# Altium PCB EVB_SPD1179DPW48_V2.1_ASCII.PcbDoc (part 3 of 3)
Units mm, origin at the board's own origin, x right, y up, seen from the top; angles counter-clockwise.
Board outline 135 x 90 mm, 4 copper layers (Top Layer, GND, L3, Bottom Layer), stack 0.603 mm thick; 322 components, 156 nets, 727 pads, 939 vias.
Unrouted connection lines stored in the file: 172.
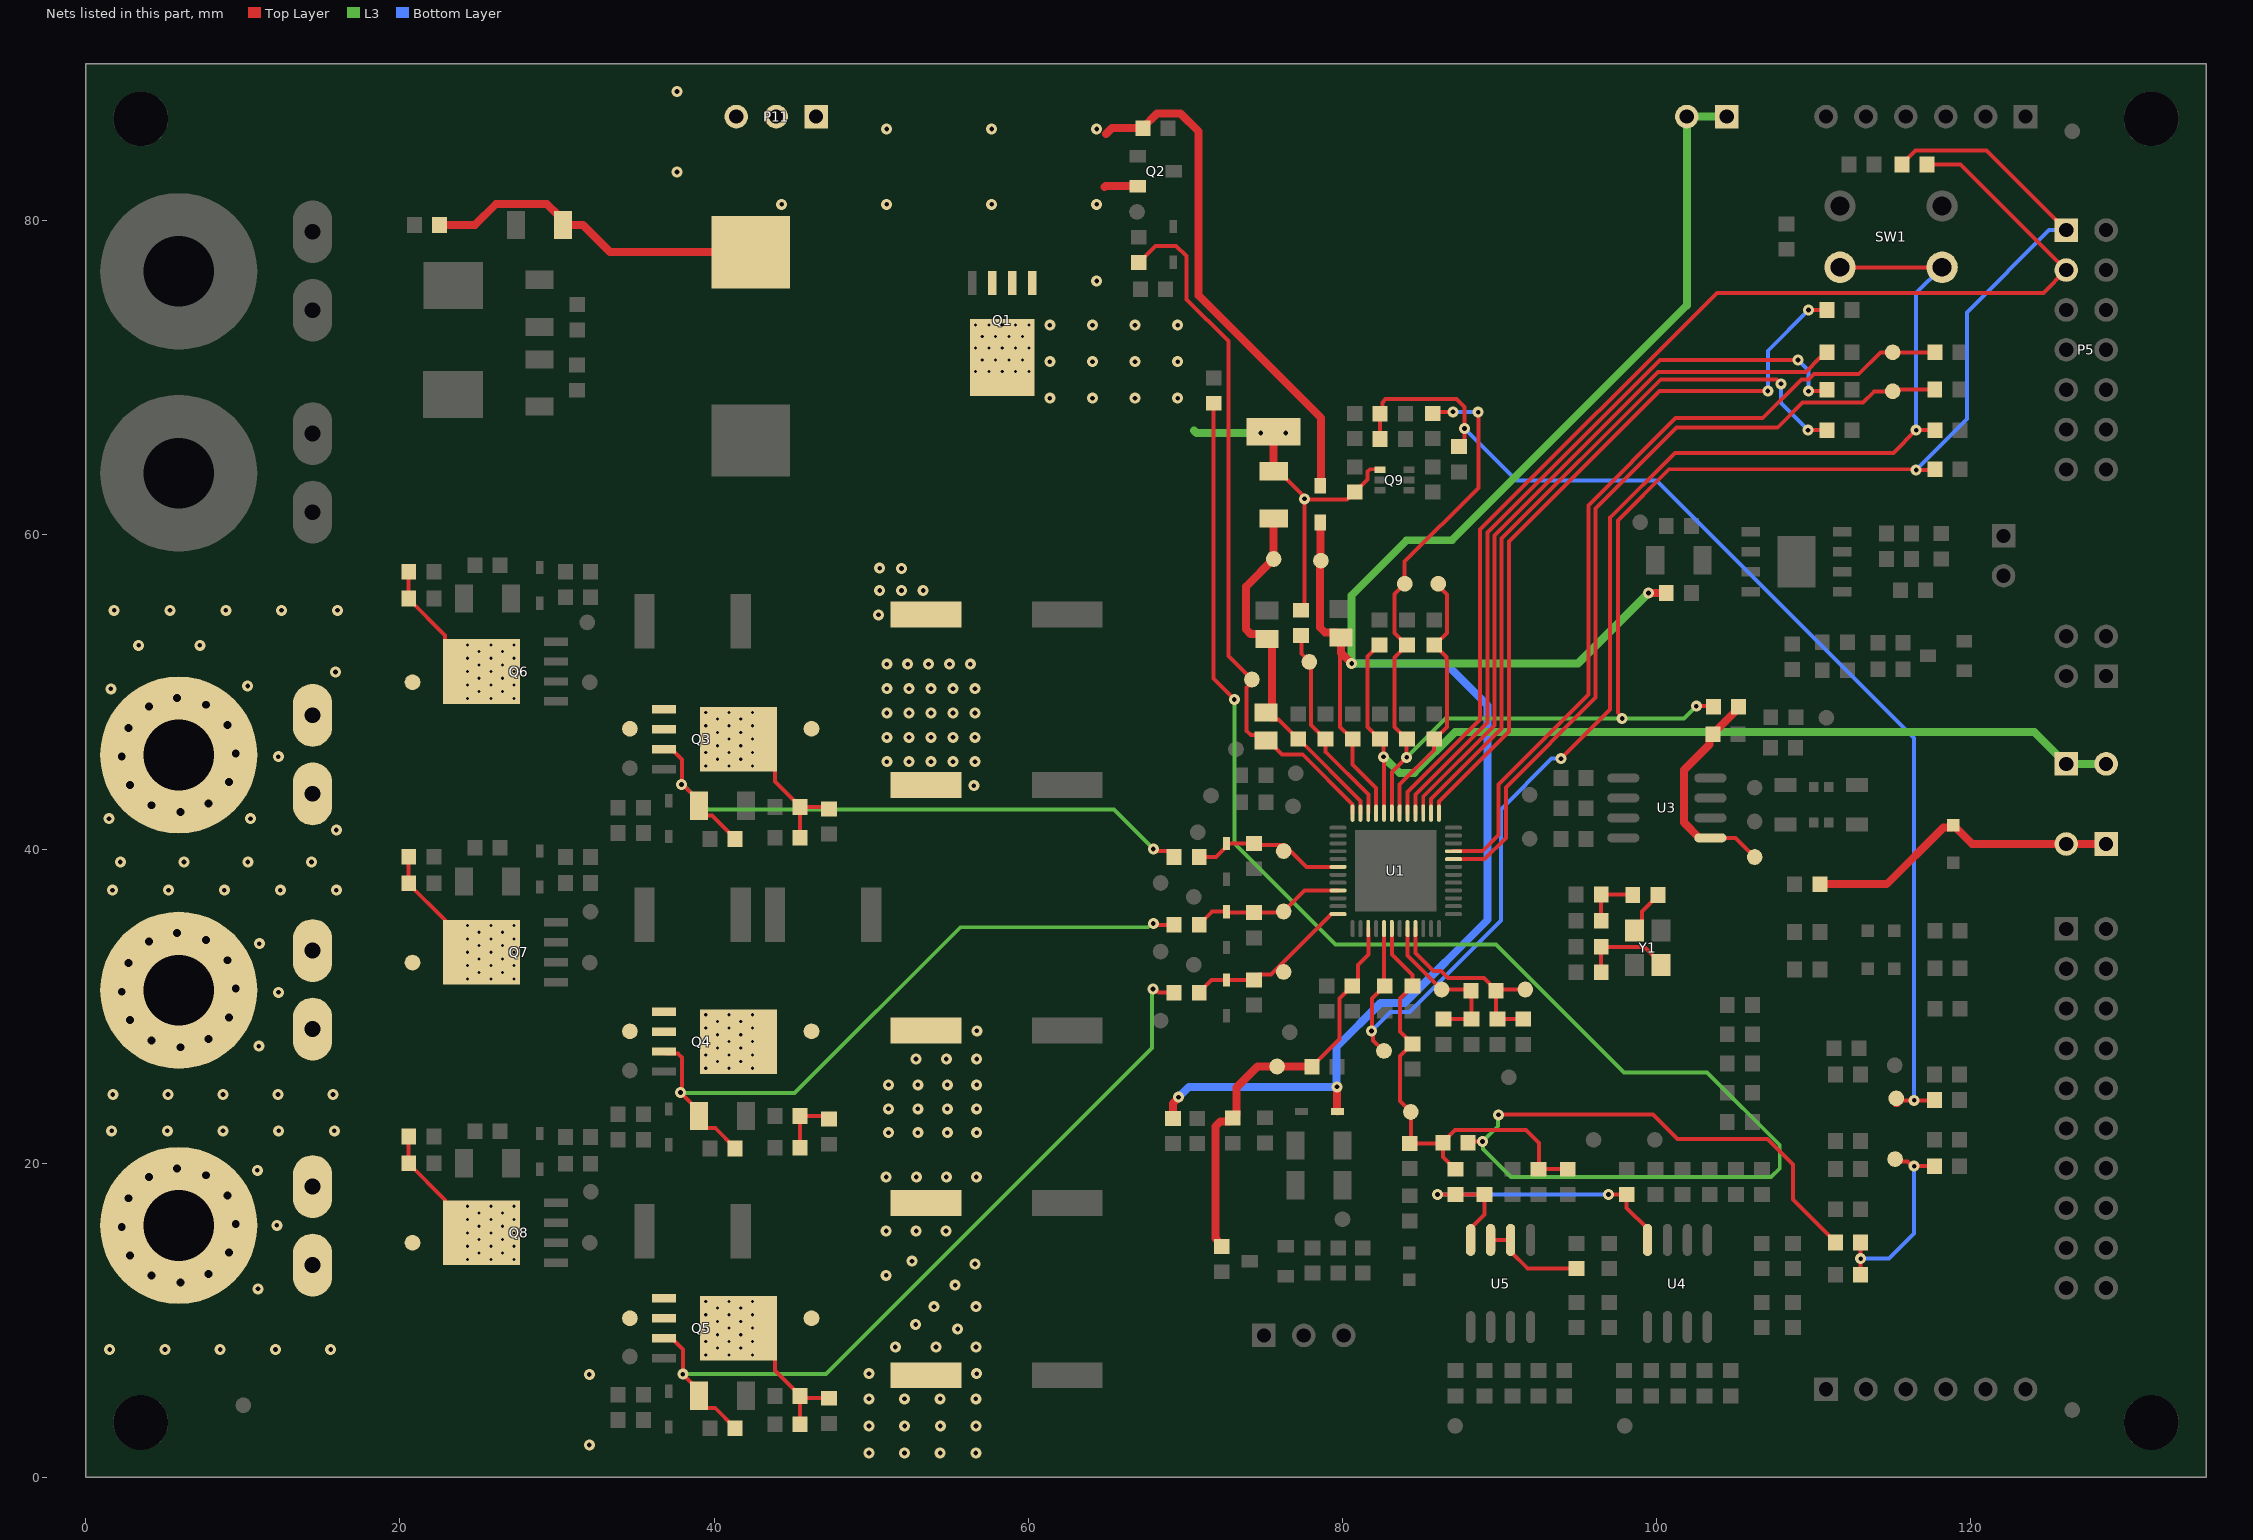
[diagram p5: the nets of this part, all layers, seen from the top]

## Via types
v1: diameter 0.7, hole 0.3, Top Layer to Bottom Layer, tented both sides, 693 vias
v2: diameter 0.5, hole 0.2, Top Layer to Bottom Layer, tented both sides, 154 vias
v3: diameter 0.9, hole 0.5, Top Layer to Bottom Layer, 60 vias
v4: diameter 0.5, hole 0.2, Top Layer to Bottom Layer, 32 vias

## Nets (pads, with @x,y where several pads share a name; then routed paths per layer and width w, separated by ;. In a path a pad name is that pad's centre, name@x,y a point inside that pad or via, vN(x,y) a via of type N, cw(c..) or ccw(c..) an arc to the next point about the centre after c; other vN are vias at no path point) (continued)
NetR107_1: R107.1 R108.1 R109.1 | length 122.3
  Top Layer w0.254: R109.1@71.806,68.39 71.806,50.851 v1(73.127,49.53) ; R107.1@87.998,21.311 88.072,21.384 v1(88.925,21.384) ; v1(89.941,23.089) 89.967,23.114 99.771,23.114 101.346,21.539 107.075,21.539 108.687,19.927 108.687,17.691 111.392,14.986 R108.1@111.392,14.961
  L3 w0.254: v1(73.127,49.53) 73.127,40.361 79.553,33.934 89.789,33.934 97.942,25.781 103.226,25.781 107.848,21.158 107.848,19.681 107.293,19.126 90.729,19.126 88.961,20.894 88.961,21.349 v1(88.925,21.384) 89.899,22.358 89.899,23.046 v1(89.941,23.089)
NetR110_2: R110.2 U5.6 U5.7 | length 6.6
  Top Layer w0.254: U5.7@89.443,15.117 U5.6@90.713,15.117 90.713,14.388 91.804,13.297 R110.2@94.904,13.297
NetR123_1: R123.1 Y1.3 | length 2.9
  Top Layer w0.254: Y1.3@98.591,34.831 99.064,35.304 99.064,36.034 100.089,37.059 R123.1@100.089,37.084
NTCAD: C73.2 NTCAD.1 R104.1 R108.2 | length 13.1
  Top Layer w0.254: C73.2@112.992,12.903 R108.2@112.992,14.961 R108.2@112.992,14.986 ; NTCAD.1@115.189,20.269 115.332,20.126 115.973,20.126 116.288,19.812 v1(116.408,19.812) R104.1@117.704,19.812
  Bottom Layer w0.254: v1(113.005,13.924) 114.812,13.924 116.408,15.519 v1(116.408,19.812)
PGAIN: C51.1 C53.2 PGAIN.1 R58.2 U1.44 | length 10.3
  Top Layer w0.254: U1.44@84.152,34.941 84.152,33.231 PGAIN.1@86.319,31.064 88.109,31.064 C51.1@88.186,30.988 88.224,30.95 R58.2@88.224,29.172 C53.2@86.446,29.172
PGAIP: C51.2 C52.2 PGAIP.1 R54.2 U1.45 | length 13.1
  Top Layer w0.254: U1.45@84.652,34.941 84.652,33.378 85.801,32.228 86.293,32.228 86.728,31.793 89.006,31.793 89.786,31.013 C51.2@89.786,30.988 ; C52.2@91.526,29.172 R54.2@89.875,29.172 89.786,29.261 C51.2@89.786,30.988 ; PGAIP.1@91.653,31.064 89.862,31.064 C51.2@89.786,30.988
PWM/LIN: D18.2 P25.1 P25.2 R21.1 | length 20.3
  Top Layer w0.508: R21.1@110.401,37.77 114.656,37.77 118.271,41.385 118.751,41.385 D18.2@118.897,41.531 120.101,40.327 P25.2@126.086,40.327 P25.1@128.626,40.327
PWM/LIN_MCU: C78.2 LIN.1 R66. R84.1 R111.1 U1.39 | length 26.8
  Top Layer w0.254: R111.1@73.025,22.873 R111.1@73.262,23.11 ; R66.@78.067,26.137 78.067,26.162 79.808,27.903 79.808,30.484 80.604,31.28 C78.2@80.629,31.28 ; C78.2@80.764,31.28 80.985,31.5 80.985,32.615 81.652,33.282 U1.39@81.652,34.941
  Top Layer w0.508: R84.1@72.314,14.694 72.289,14.694 72.068,14.915 72.068,15.077 71.933,15.212 71.933,22.354 72.23,22.652 72.804,22.652 R111.1@73.025,22.873 ; R111.1@73.262,23.11 73.262,24.824 74.6,26.162 LIN.1@75.844,26.162 R66.@78.042,26.162
TCK/SWC: R16.2 U1.16 | length 47.6
  Top Layer w0.254: U1.16@84.652,42.291 84.652,43.483 89.23,48.061 89.23,60.152 100.224,71.145 v1(109.017,71.145) ; v1(109.677,69.159) 110.777,69.159 R16.2@110.858,69.24
  Bottom Layer w0.254: v1(109.017,71.145) 109.677,70.485 v1(109.677,69.159)
TDI: R13.2 U1.13 | length 47
  Top Layer w0.254: U1.13@86.152,42.291 86.154,42.293 86.154,43.045 90.602,47.493 90.602,59.583 100.188,69.17 v1(107.086,69.17) ; v1(109.677,74.32) R13.2@110.858,74.32
  Bottom Layer w0.254: v1(107.086,69.17) 107.086,71.73 v1(109.677,74.32)
TDO: R18.2 U1.14 | length 46.3
  Top Layer w0.254: U1.14@85.652,42.291 85.652,43.189 90.145,47.682 90.145,59.773 100.273,69.901 107.65,69.901 v1(107.923,69.628) ; v1(109.652,66.675) 110.85,66.675 R18.2@110.858,66.667
  Bottom Layer w0.254: v1(107.923,69.628) 107.923,68.404 v1(109.652,66.675)
TMS/SWD: R14.2 U1.15 | length 45.6
  Top Layer w0.254: U1.15@85.152,42.291 85.152,43.336 89.687,47.872 89.687,59.962 100.109,70.383 109.513,70.383 110.385,71.255 110.51,71.255 110.858,71.603 R14.2@110.858,71.628
TRSTn: P5.3 R12.1 U1.17 | length 75.8
  Top Layer w0.254: U1.17@84.152,42.291 84.152,43.629 88.773,48.251 88.773,60.341 103.845,75.413 124.628,75.413 P5.3@126.086,76.87 119.364,83.591 R12.1@117.234,83.591
UART_RX: R15.1 RX.1 U1.9 | length 52.8
  Top Layer w0.254: U1.9@87.077,39.866 88.913,39.866 89.954,40.906 89.954,44.118 95.67,49.835 95.67,61.888 101.219,67.437 106.766,67.437 109.219,69.89 109.666,69.89 110.033,70.256 112.878,70.256 114.249,71.628 R15.1@117.729,71.628
UART_TX: R17.1 TX.1 U1.8 | length 52
  Top Layer w0.254: U1.8@87.077,39.366 89.06,39.366 90.411,40.717 90.411,43.929 96.127,49.645 96.127,61.699 101.281,66.853 107.721,66.853 109.296,68.428 113.145,68.428 113.864,69.147 TX.1@115.037,69.147 115.155,69.266 R17.1@117.716,69.266
VBAT: C35.2 C36.2 D12.1 D16.2 P10.1 P10.2 R49.1 R64.2 U1.21 VBAT.1 | length 144.6
  Top Layer w0.254: C35.2@79.908,53.481 79.856,53.429 79.856,47.783 80.636,47.003 C36.2@80.661,47.003 80.661,45.383 82.152,43.893 U1.21@82.152,42.291
  Top Layer w0.508: R64.2@69.215,22.847 69.215,23.82 69.571,24.176 v1(69.571,24.206) ; D12.1@78.595,60.798 78.595,58.412 VBAT.1@78.638,58.369 78.588,58.318 78.588,54.1 78.885,53.802 79.587,53.802 C35.2@79.908,53.481 79.908,52.502 v1(80.594,51.816) ; v1(79.654,24.867) 79.654,23.324 D16.2@79.686,23.292 ; v1(99.492,56.312) R49.1@100.622,56.312
  L3 w0.508: v1(99.492,56.312) 94.996,51.816 v1(80.594,51.816) 80.594,56.159 84.099,59.665 86.97,59.665 101.93,74.625 P10.2@101.93,86.639 P10.1@104.47,86.639
  Bottom Layer w0.508: v1(69.571,24.206) 70.231,24.867 v1(79.654,24.867) ; v1@79.642,24.892 79.642,27.419 82.433,30.21 83.957,30.21 89.256,35.509 89.256,49.149 86.589,51.816 v1(80.594,51.816)
VBAT1: C9.2 C10.1 C11.2 D12.2 L1.2 P11.1 P11.2 P11.3 Q1.1 Q1.2 Q1.3 Q2.2 | length 56.7
  Top Layer w0.508: C11.2@22.517,79.731 24.77,79.731 26.102,81.062 29.373,81.062 30.059,80.377 30.38,80.056 C10.1@30.38,79.731 31.648,79.731 33.37,78.009 L1.2@42.342,78.009 ; 64.872,82.169 64.912,82.21 Q2.2@66.973,82.21 ; 64.948,85.522 65.329,85.903 C9.2@67.297,85.903 67.297,85.928 68.204,86.835 69.706,86.835 70.841,85.7 70.841,75.26 78.638,67.462 D12.2@78.638,63.143
  other v1: 64.364,76.175 44.304,81.051 50.99,81.051 57.677,81.051 64.364,81.051 37.643,83.112 50.99,85.852 57.677,85.852 64.364,85.852 37.643,88.24
VBAT_D: C1.1 C5.1 C6.1 C14.1 C15.1 C16.2 C17.2 C18.2 C20.2 C21.2 C22.2 C56.1 C68.1 C69.1 D.1@46.203,10.135 D.1@46.203,28.397 D.1@46.203,47.66 Q1.5 Q3.5 Q4.5 Q5.5 Q9.4 R39.2 R43.1 R93.1 VBAT_D.1 | length 45
  Top Layer w0.254: v2(42.443,7.804) 43.631,7.804 43.866,7.569 43.866,6.819 45.479,5.207 C22.2@45.479,5.182 ; v2(42.443,45.301) 43.631,45.301 43.866,45.066 43.866,44.316 45.479,42.704 C20.2@45.479,42.679 ; C69.1@45.479,3.378 C22.2@45.479,5.182 ; C68.1@45.479,20.996 C21.2@45.479,23.003 47.13,23.003 C16.2@47.32,22.812 ; C56.1@45.479,40.723 C20.2@45.479,42.679 ; C18.2@47.32,5.042 45.618,5.042 C22.2@45.479,5.182 ; C17.2@47.32,42.564 47.206,42.679 C20.2@45.479,42.679 ; R43.1@75.625,64.06 75.95,64.06 v1@77.597,62.413 ; R39.2@77.368,55.207 77.597,55.435 77.597,60.041 ; 77.596,60.042 77.596,60.561 v1(77.597,62.306) v1@77.597,62.413 ; Q9.4@82.392,64.15 82.337,64.094 82.245,64.186 81.759,64.186 81.61,64.037 81.61,63.532 81.154,63.076 81.104,63.076 80.284,62.255 77.755,62.255 v1@77.597,62.413
  Top Layer w0.508: R43.1@75.625,64.06 VBAT_D.1@75.625,66.573
  L3 w0.508: 70.561,66.65 70.714,66.497 v1(74.799,66.497) v1(76.399,66.497)
  other v1: 49.86,1.549 52.129,1.549 54.398,1.549 56.667,1.549 32.055,2.057 49.86,3.277 52.132,3.277 54.404,3.277 56.676,3.277 49.86,5.004 52.129,5.004 54.398,5.004 56.667,5.004 32.055,6.553 49.86,6.604 56.718,6.604 51.537,8.306 54.131,8.306 56.676,8.306 55.506,9.451 52.832,9.728 54,10.871 56.676,10.871 55.347,12.243 50.961,12.866 56.617,13.589 52.603,13.767 50.961,15.686 52.866,15.686 54.771,15.686 50.961,19.126 52.874,19.126 54.787,19.126 56.701,19.126 51.105,21.946 52.976,21.946 54.847,21.946 56.718,21.946 51.105,23.47 52.976,23.47 54.847,23.47 56.718,23.47 51.105,24.994 52.976,24.994 54.847,24.994 56.718,24.994 52.857,26.645 54.788,26.645 56.718,26.645 56.726,28.436 56.54,44.044 51.003,45.568 52.407,45.568 53.81,45.568 55.213,45.568 56.617,45.568 51.003,47.12 52.407,47.12 53.81,47.12 55.213,47.12 56.617,47.12 51.003,48.673 52.407,48.673 53.81,48.673 55.213,48.673 56.617,48.673 51.003,50.216 52.407,50.216 53.81,50.216 55.213,50.216 56.617,50.216 51.003,51.779 52.33,51.779 53.657,51.779 54.985,51.779 56.312,51.779 50.47,54.915 50.546,56.464 51.93,56.464 53.315,56.464 51.93,57.861 50.546,57.887 61.377,68.707 64.092,68.707 66.806,68.707 69.52,68.707 61.377,71.031 64.092,71.031 66.806,71.031 69.52,71.031 61.377,73.355 64.092,73.355 66.806,73.355 69.52,73.355
  other v2: 39.472,7.804 40.957,7.804 40.215,8.23 41.7,8.23 39.472,8.655 40.957,8.655 42.443,8.655 40.215,9.081 41.7,9.081 39.472,9.506 42.443,9.506 40.215,9.931 41.7,9.931 39.472,10.357 40.957,10.357 42.443,10.357 40.215,10.782 41.7,10.782 39.472,11.208 40.957,11.208 42.443,11.208 39.472,26.053 40.957,26.053 42.443,26.053 40.215,26.478 41.7,26.478 39.472,26.904 40.957,26.904 42.443,26.904 40.215,27.329 41.7,27.329 39.472,27.754 42.443,27.754 40.215,28.18 41.7,28.18 39.472,28.605 40.957,28.605 42.443,28.605 40.215,29.031 41.7,29.031 39.472,29.456 40.957,29.456 42.443,29.456 39.472,45.301 40.957,45.301 40.215,45.727 41.7,45.727 39.472,46.152 40.957,46.152 42.443,46.152 40.215,46.577 41.7,46.577 39.472,47.003 42.443,47.003 40.215,47.428 41.7,47.428 39.472,47.854 40.957,47.854 42.443,47.854 40.215,48.279 41.7,48.279 39.472,48.705 40.957,48.705 42.443,48.705 56.648,70.409 57.499,70.409 58.35,70.409 59.201,70.409 60.052,70.409 57.074,71.152 57.925,71.152 58.776,71.152 59.627,71.152 56.648,71.895 57.499,71.895 59.201,71.895 60.052,71.895 57.074,72.638 57.925,72.638 58.776,72.638 59.627,72.638 56.648,73.381 57.499,73.381 58.35,73.381 59.201,73.381 60.052,73.381
  other v4: 40.957,9.506 40.957,27.754 40.957,47.003 58.35,71.895
VBATCP: C38.2 C39.2 C49.2 R43.2 U1.23 VBATCP.1 | length 23.5
  Top Layer w0.254: C49.2@75.143,48.603 75.491,48.255 75.923,48.255 77.175,47.003 C39.2@77.2,47.003 77.225,47.003 81.15,43.078 81.15,42.293 U1.23@81.152,42.291
  Top Layer w0.508: C49.2@75.143,48.703 75.193,48.703 75.514,49.024 75.514,53.075 74.888,53.701 74.161,53.701 73.863,53.998 73.863,56.709 VBATCP.1@75.625,58.471 R43.2@75.625,61.06
VBATD_DIV: C83.2 R87.1 R88.1 R98.1 VBATdiv.1 | length 73.1
  Top Layer w0.254: R88.1@82.41,66.116 R98.1@82.41,67.716 82.546,67.852 82.546,68.449 82.753,68.656 87.267,68.656 87.782,68.141 v1(87.782,66.777) 87.782,65.971 87.434,65.623 C83.2@87.427,65.623 ; VBATdiv.1@115.189,23.724 115.391,23.724 115.67,24.003 v1(116.408,24.003) 117.678,24.003 R87.1@117.704,24.028
  Bottom Layer w0.254: v1(87.782,66.777) 91.084,63.475 100,63.475 116.408,47.066 v1(116.408,24.003)
VBATM: C37.2 R39.1 U1.22 VBATM.1 | length 13.1
  Top Layer w0.254: R39.1@77.403,53.597 77.403,52.439 77.902,51.94 VBATM.1@77.902,51.918 78.005,51.815 78.005,47.903 78.905,47.003 C37.2@78.93,47.003 78.93,46.199 81.652,43.478 U1.22@81.652,42.291
VCAP12: C29.2 C30.2 U1.18 VCAP12.1 | length 16.8
  Top Layer w0.254: U1.18@83.652,42.291 83.652,44.104 85.843,46.296 85.843,46.994 C30.2@85.852,47.003 85.877,47.003 86.657,47.783 86.657,52.053 86.639,52.07 86.639,52.222 C29.2@85.877,52.984 ; C29.2@85.852,52.984 C29.2@85.877,52.984 ; VCAP12.1@86.106,56.896 86.106,56.752 86.657,56.201 86.657,53.764 C29.2@85.877,52.984
VCP: C49.1 R5.1 U1.24 VCP.1 | length 45.1
  Top Layer w0.254: R5.1@67.031,77.356 67.056,77.356 68.106,78.406 69.422,78.406 70.079,77.749 70.079,75.006 72.746,72.339 72.746,52.299 VCP.1@74.244,50.8 74.244,50.608 73.914,50.278 73.914,47.523 74.185,47.252 74.918,47.252 76.146,46.025 77.479,46.025 80.652,42.853 U1.24@80.652,42.291
VDD3: C40.2 C41.2 C72.2 R82.1 R96.1 R106.2 R107.2 U1.42 VDD3.1 | length 30.1
  Top Layer w0.254: U1.42@83.152,34.941 83.152,33.291 84.456,31.987 84.456,31.289 C41.2@84.464,31.28 ; C41.2@84.439,31.28 83.66,30.5 83.66,28.402 84.091,27.97 84.091,27.945 C40.2@84.439,27.597 ; R96.1@87.208,19.621 87.183,19.621 86.398,20.406 R107.2@86.398,21.311 ; C72.2@94.345,19.621 R82.1@92.491,19.621 92.466,19.621 92.527,19.682 92.527,21.283 91.694,22.115 87.178,22.115 86.398,21.336 R107.2@86.398,21.311 ; C40.2@84.439,27.597 C40.2@84.464,27.597 C40.2@84.439,27.597 ; C40.2@84.439,27.597 83.66,26.817 83.66,23.97 VDD3.1@84.363,23.266 84.363,21.336 R106.2@84.287,21.26 86.347,21.26 R107.2@86.398,21.311
VDD5: C31.2 C32.2 P5.1 R12.2 R20.2 R48.2 R97.1 U1.19 VDD5.1 | length 120.1
  Top Layer w0.254: U1.19@83.152,42.291 83.152,44.899 v1(84.099,45.847) 84.099,46.981 C32.2@84.122,47.003 84.097,47.003 83.317,47.783 83.317,52.205 C31.2@84.097,52.984 ; C31.2@84.122,52.984 C31.2@84.097,52.984 ; R97.1@85.765,67.741 85.867,67.843 v1(87.046,67.843) ; v1(88.646,67.818) 88.671,67.793 88.671,63.004 83.972,58.305 VDD5.1@83.972,56.896 83.317,56.24 83.317,53.764 C31.2@84.097,52.984 ; v1(97.815,48.311) 97.815,48.403 97.536,48.683 97.536,60.935 100.787,64.186 116.487,64.186 v1(116.532,64.141) 117.684,64.141 R20.2@117.729,64.186 ; v1(102.54,49.098) 103.594,49.098 R48.2@103.619,49.073 ; R12.2@115.634,83.591 115.634,83.616 116.49,84.472 121.023,84.472 P5.1@126.086,79.41
  L3 w0.254: v1(84.099,45.847) 86.563,48.311 v1(97.815,48.311) 101.752,48.311 v1(102.54,49.098)
  Bottom Layer w0.254: v1(87.046,67.843) 87.058,67.831 88.633,67.831 v1(88.646,67.818) ; v1(116.532,64.141) 119.761,67.37 119.761,74.168 125.003,79.41 P5.1@126.086,79.41
VDD5EXT: C33.2 C84.2 P8.1 P8.2 U1.20 | length 60.2
  Top Layer w0.254: C33.2@82.607,52.75 C33.2@82.372,52.985 82.347,52.985 81.614,52.251 81.593,52.251 81.593,47.783 82.373,47.003 C84.2@82.398,47.003 82.626,46.774 v1(82.626,45.872) 82.65,45.849 82.65,42.293 U1.20@82.652,42.291
  L3 w0.508: v1(82.626,45.872) 83.642,44.856 84.582,44.856 87.173,47.447 124.063,47.447 P8.1@126.086,45.425 P8.2@128.626,45.425
VIO: C61.2 R48.1 U3.5 VIO.1 | length 14.2
  Top Layer w0.254: U3.5@103.433,40.716 105.029,40.716 VIO.1@106.248,39.497
  Top Layer w0.508: U3.5@103.433,40.716 102.726,40.716 101.752,41.69 101.752,45.034 103.373,46.655 103.373,47.099 C61.2@103.594,47.32 103.594,47.345 104.998,48.75 104.998,48.852 R48.1@105.219,49.073
VOP: C70.2 C71.2 R96.2 U4.8 U5.8 | length 21.8
  Top Layer w0.254: v1(86.055,18.009) 87.195,18.009 R96.2@87.208,18.021 C70.2@89.057,18.021 89.057,16.73 88.173,15.845 U5.8@88.173,15.117 ; v1(96.952,18.009) 98.093,18.009 C71.2@98.106,18.021 98.106,17.165 99.427,15.845 U4.8@99.427,15.117
  Bottom Layer w0.254: v1(86.055,18.009) v1(96.952,18.009)
VPX_U: C28.1 C43.2 C79.1 D.1@20.803,14.935 P16.1 pad.1@5.918,16.042 Q5.1 Q5.2 Q5.3 Q8.5 R31.1 R37.2 S.1@34.646,10.135 | length 58.6
  Top Layer w0.254: C79.1@20.561,21.7 C43.2@20.561,19.998 20.561,19.973 22.879,17.655 22.879,17.501 23.114,17.266 v2(24.301,17.266) ; Q5.3@36.805,8.865 37.3,8.865 38.015,8.15 v1(38.015,6.568) 38.015,6.555 39.038,5.532 R37.2@39.038,5.207 39.038,4.882 39.486,4.434 40.054,4.434 41.338,3.149 C28.1@41.338,3.124 ; v1(67.947,31.091) 68.068,31.091 68.298,30.861 R31.1@69.288,30.861
  L3 w0.254: v1(38.015,6.568) 38.025,6.579 47.117,6.579 67.885,27.347 67.885,31.03 v1(67.947,31.091)
  other v1: 1.52,8.148 5.038,8.148 8.556,8.148 12.074,8.148 15.592,8.148 10.969,12.009 12.163,16.048 10.918,19.553 1.647,22.068 5.191,22.068 8.734,22.068 12.277,22.068 15.82,22.068
  other v2: 24.301,13.862 25.787,13.862 27.273,13.862 25.044,14.288 26.53,14.288 24.301,14.713 25.787,14.713 27.273,14.713 25.044,15.138 26.53,15.138 24.301,15.564 27.273,15.564 25.044,15.989 26.53,15.989 24.301,16.415 25.787,16.415 27.273,16.415 25.044,16.84 26.53,16.84 25.787,17.266 27.273,17.266
  other v3: 6.02,12.409 4.19,12.845 7.822,12.947 2.823,14.138 9.115,14.313 2.286,15.94 9.55,16.143 2.722,17.77 9.013,17.946 4.014,19.136 7.646,19.238 5.817,19.674
  other v4: 25.787,15.564
VPX_U0: C19.2 D3.1 R31.2 U1.36 VPXU.1 | length 10.9
  Top Layer w0.254: R31.2@70.888,30.861 70.888,30.886 71.673,31.671 D3.1@72.628,31.671 72.635,31.664 C19.2@74.381,31.664 74.729,32.012 75.452,32.012 79.306,35.866 U1.36@79.727,35.866
VPX_V: C27.1 C42.2 C76.1 D.1@20.803,32.779 P15.1 pad.1@5.918,31.017 Q4.1 Q4.2 Q4.3 Q7.5 R33.2 R38.1 S.1@34.646,28.397 | length 51.5
  Top Layer w0.254: C76.1@20.561,39.521 C42.2@20.561,37.819 20.561,37.794 22.879,35.477 22.879,35.37 23.114,35.135 v2(24.301,35.135) ; Q4.3@36.805,27.113 36.944,26.973 37.703,26.973 37.946,26.731 37.946,24.601 37.855,24.511 39.038,23.328 R33.2@39.038,23.003 39.038,22.678 39.486,22.23 40.079,22.23 41.338,20.971 C27.1@41.338,20.946 ; v1(67.97,35.261) 68.052,35.179 R38.1@69.288,35.179
  L3 w0.254: v1(37.86,24.511) 37.886,24.486 45.136,24.486 55.677,35.027 67.616,35.027 67.85,35.261 v1(67.97,35.261)
  other v1: 1.723,24.379 5.229,24.379 8.734,24.379 12.239,24.379 15.744,24.379 11.02,27.452 12.264,30.881 11.045,33.98 1.698,37.384 5.26,37.384 8.823,37.384 12.385,37.384 15.947,37.384
  other v2: 24.301,31.731 25.787,31.731 27.273,31.731 25.044,32.156 26.53,32.156 24.301,32.582 25.787,32.582 27.273,32.582 25.044,33.007 26.53,33.007 24.301,33.433 27.273,33.433 25.044,33.858 26.53,33.858 24.301,34.284 25.787,34.284 27.273,34.284 25.044,34.709 26.53,34.709 25.787,35.135 27.273,35.135
  other v3: 6.02,27.385 4.19,27.821 7.822,27.922 2.823,29.113 9.115,29.289 2.286,30.916 9.55,31.119 2.722,32.745 9.013,32.921 4.014,34.112 7.646,34.214 5.817,34.649
  other v4: 25.787,33.433
VPX_V0: C23.2 D4.1 R38.2 U1.33 VPXV.1 | length 9.9
  Top Layer w0.254: R38.2@70.888,35.179 70.888,35.204 71.698,36.014 D4.1@72.628,36.014 72.689,35.954 VPXV.1@76.184,35.954 ; VPXV.1@76.26,36.03 VPXV.1@76.184,35.954 ; U1.33@79.727,37.366 77.596,37.366 VPXV.1@76.184,35.954
VPX_W: C25.2 C26.1 C75.1 D.1@20.803,50.622 P14.1 pad.1@5.918,45.993 Q3.1 Q3.2 Q3.3 Q6.5 R32.2 R44.1 S.1@34.646,47.66 | length 48.4
  Top Layer w0.254: C75.1@20.561,57.658 C25.2@20.561,55.956 20.561,55.931 22.879,53.614 22.879,53.238 23.114,53.003 v2(24.301,53.003) ; Q3.3@36.805,46.362 37.3,46.362 37.961,45.701 37.961,44.159 v1(37.922,44.12) 37.998,44.12 39.038,43.08 39.038,42.587 39.486,42.139 39.871,42.139 41.338,40.672 C26.1@41.338,40.647 ; v1(67.97,40.005) 68.091,40.005 68.226,39.87 68.94,39.87 69.288,39.522 R44.1@69.288,39.497
  L3 w0.254: v1(37.922,44.12) 38.024,44.12 39.624,42.52 65.456,42.52 v1(67.97,40.005)
  other v1: 2.202,39.181 6.258,39.181 10.313,39.181 14.369,39.181 15.951,41.224 1.473,41.935 10.483,41.935 12.261,45.886 1.593,50.204 10.305,50.382 15.893,51.271 3.371,52.973 7.257,52.973 1.803,55.208 5.357,55.208 8.912,55.208 12.466,55.208 16.02,55.208
  other v2: 24.301,49.6 25.787,49.6 27.273,49.6 25.044,50.025 26.53,50.025 24.301,50.451 25.787,50.451 27.273,50.451 25.044,50.876 26.53,50.876 24.301,51.302 27.273,51.302 25.044,51.727 26.53,51.727 24.301,52.153 25.787,52.153 27.273,52.153 25.044,52.578 26.53,52.578 25.787,53.003 27.273,53.003
  other v3: 6.02,42.361 4.19,42.796 7.822,42.898 2.823,44.089 9.115,44.265 2.286,45.891 9.55,46.094 2.722,47.721 9.013,47.897 4.014,49.088 7.646,49.189 5.817,49.625
  other v4: 25.787,51.302
VPX_W0: C24.2 D5.1 R44.2 U1.30 VPXW.1 | length 9.9
  Top Layer w0.254: R44.2@70.888,39.497 71.957,39.497 72.628,40.168 D5.1@72.628,40.358 72.635,40.351 C24.2@74.381,40.351 ; C24.2@74.381,40.272 76.326,40.272 77.731,38.866 U1.30@79.727,38.866
XIN: C12.2 R1.1 Y1.1 | length 6
  Top Layer w0.254: C12.2@96.482,32.156 R1.1@96.482,33.782 99.24,33.782 100.291,32.731 Y1.1@100.291,32.631
XOUT: C13.2 R120.1 R123.2 | length 3.7
  Top Layer w0.254: R120.1@96.482,35.433 C13.2@96.482,37.109 98.463,37.109 R123.2@98.489,37.084 R123.2@98.489,37.059
XRSTn: C7.2 R19.1 SW1.3 SW1.4 U1.41 XRSTn.1 | length 89
  Top Layer w0.254: v1(81.856,28.42) 81.941,28.335 81.941,27.831 82.509,27.263 XRSTn.1@82.509,27.153 ; v1@81.899,28.426 81.899,30.281 81.899,30.501 82.678,31.28 C7.2@82.703,31.28 82.652,31.332 U1.41@82.652,34.941 ; v1(93.918,45.756) 97.053,48.891 97.053,61.099 101.182,65.227 115.087,65.227 v1(116.535,66.675) 117.721,66.675 R19.1@117.729,66.667 ; SW1.3@111.685,77.044 SW1.4@118.185,77.044
  Bottom Layer w0.254: v1(81.856,28.42) 83.062,29.626 84.261,29.626 90.094,35.458 90.094,42.52 93.33,45.756 v1(93.918,45.756) ; v1(116.535,66.675) 116.535,75.394 SW1.4@118.185,77.044
pads on no net: MARK7.1 MARK8.1 MARK9.1 P2.17 P2.18 P2.19 P2.20 SC1.3 SC2.3 SC3.3 SC4.3 U2.3 U2.4 U2.6

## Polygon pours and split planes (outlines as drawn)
GND on Top Layer "GND_L01_P063" (solid, remove dead copper, pour order 63): 71.45,82.855 71.45,7.112 78.511,7.112 80.67,4.953 80.67,0.356 81.001,0.025 122.555,0.025 129.642,7.112 135.103,7.112 135.103,82.855 129.819,82.855 122.733,89.941 80.67,89.941 80.67,85.039 78.486,82.855
GND on Top Layer "NONET_L-01_P-001" (solid, remove dead copper, pour order 21): 0.864,82.906 0.381,82.423 0.381,71.704 1.27,70.815 18.263,70.815 20.269,72.822 35.611,72.822 35.789,73 35.789,82.982 25.349,82.982 23.317,85.014 23.317,89.154 7.163,89.154 7.163,85.014 5.055,82.906
KL30 on Top Layer "KL30_L01_P013" (solid, remove dead copper, pour order 13): 0.203,70.383 0.203,56.515 26.822,56.515 29.845,59.538 49.073,59.538 49.174,59.639 49.174,72.238 48.997,72.415 20.549,72.415 18.669,70.536 0.356,70.536
GND on Top Layer "GND_L01_P009" (solid, remove dead copper, pour order 9): 47.625,40.361 47.32,40.056 47.32,36.576 49.581,36.576 49.759,36.398 49.759,35.255 49.555,35.052 47.32,35.052 47.32,31.115 47.65,30.785 56.998,30.785 58.318,29.464 58.318,1.092 59.055,0.356 70.51,0.356 71.298,1.143 71.298,60.706 58.75,60.706 58.318,60.274 58.318,41.224 57.455,40.361
IBS+ on Top Layer "IBS+_L01_P008" (solid, remove dead copper, pour order 8): 39.472,40.107 38.964,39.599 38.964,36.627 41.046,36.627 41.275,36.398 41.275,35.179 41.148,35.052 38.964,35.052 38.964,31.09 39.218,30.836 46.584,30.836 46.939,31.191 46.939,35.052 44.475,35.052 44.171,35.357 44.171,36.449 44.298,36.576 46.939,36.576 46.939,40.056 46.888,40.107
VBAT_D on Top Layer "VBAT_D_L01_P006" (solid, remove dead copper, pour order 6): 38.456,11.913 38.456,4.343 41.758,1.041 51.054,1.041 51.054,12.548 49.708,13.894 49.555,13.741 49.555,13.386 48.743,12.573 39.116,12.573
IBS+ on Top Layer "IBS+_L01_P004" (solid, remove dead copper, pour order 4): 39.268,20.371 38.989,20.091 38.989,16.485 41.123,16.485 41.402,16.205 41.402,15.164 41.148,14.91 38.989,14.91 38.989,12.751 48.235,12.751 48.514,13.03 48.514,20.117 48.26,20.371
VPX_W on Top Layer "VPX_W_L01_P002" (solid, remove dead copper, pour order 2): 0.864,56.032 27.026,56.032 28.372,54.686 28.372,49.276 28.88,48.768 32.893,48.768 33.401,49.276 38.506,49.276 38.506,46.076 31.191,38.76 0.864,38.76
VPX_V on Top Layer "VPX_V_L01_P001" (solid, remove dead copper, pour order 1): 0.483,38.125 26.619,38.125 28.321,36.424 28.321,30.963 29.032,30.251 38.202,30.251 38.354,30.099 38.354,25.603 37.744,24.994 35.865,23.114 0.508,23.114 0.483,23.139
VPX_U on Top Layer "VPX_U_L01_P000" (solid, remove dead copper, pour order 0): 0.762,22.809 24.257,22.809 28.27,18.796 28.27,13.157 29.058,12.37 38.1,12.37 38.1,7.95 37.414,7.264 0.762,7.264
VBAT1 on Top Layer "VBAT1_L01_P014" (solid, remove dead copper, pour order 14): 36.246,88.468 36.246,73.025 63.729,73.025 65.557,74.854 65.557,88.468
VBAT_D on Top Layer "VBAT_D_L01_P012" (solid, remove dead copper, pour order 12): 39.091,49.632 38.735,49.276 38.735,44.526 42.393,40.869 57.252,40.869 57.937,41.554 57.937,60.096 59.004,61.163 71.247,61.163 71.247,73.076 69.901,74.422 51.613,74.422 49.657,72.466 49.657,51.308 47.981,49.632
IWS+ on Top Layer "IWS+_L01_P010" (solid, remove dead copper, pour order 10): 28.753,54.915 28.753,54.661 28.575,54.483 28.575,49.428 29.185,48.819 32.664,48.819 33.604,49.759 38.608,49.759 38.608,53.67 38.506,53.772 35.89,53.772 35.763,53.899 35.763,54.991 36.144,55.372 38.532,55.372 38.557,55.397 38.557,58.953 38.506,59.004 32.766,59.004 31.521,57.76
IVS+ on Top Layer "IVS+_L01_P007" (solid, remove dead copper, pour order 7): 28.626,36.373 28.626,31.217 29.261,30.582 38.125,30.582 38.43,30.886 38.43,34.9 38.303,35.027 36.17,35.027 35.814,35.382 35.814,36.373 36.068,36.627 38.405,36.627 38.481,36.703 38.481,39.776 37.77,40.488 32.487,40.488 28.88,36.881
VBAT_D on Top Layer "VBAT_D_L01_P005" (solid, remove dead copper, pour order 5): 38.938,30.455 38.71,30.226 38.71,24.816 40.462,23.063 45.872,23.063 49.276,19.66 49.276,1.067 58.014,1.067 58.014,28.931 56.49,30.455
IUS+ on Top Layer "IUS+_L01_P003" (solid, remove dead copper, pour order 3): 28.677,13.259 29.007,12.929 38.405,12.929 38.405,14.91 35.941,14.91 35.916,14.935 35.916,16.231 36.17,16.485 38.405,16.485 38.405,20.168 38.024,20.549 30.734,20.549 28.677,18.491
GND on Top Layer "GND_L01_P059" (solid, remove dead copper, pour order 59): 30.632,89.027 30.632,84.963 28.219,82.55 35.355,82.55 35.738,82.933 35.738,88.748 35.458,89.027
IBS+ on Top Layer "IBS+_L01_P011" (solid, remove dead copper, pour order 11): 39.218,58.979 39.141,58.903 39.141,55.397 39.167,55.372 41.123,55.372 41.3,55.194 41.3,53.924 41.148,53.772 38.938,53.772 38.887,53.721 38.887,49.835 47.828,49.835 49.301,51.308 49.301,58.852 49.174,58.979
GND on Bottom Layer "GND_L04_P069" (solid, remove dead copper, pour order 69): 17.247,72.619 17.247,72.339 30.15,59.436 52.095,59.436 58.42,53.111 66.246,53.111 71.247,58.112 71.247,67.691 71.044,67.894 62.332,67.894 53.95,76.276 19.863,76.276 18.821,75.235
VBAT_D on Bottom Layer "VBAT_D_L04_P068" (solid, remove dead copper, pour order 68): 55.016,74.803 71.349,74.803 71.425,74.727 71.425,68.224 71.069,67.869 55.016,67.869
VBAT_D on Bottom Layer "NONET_L-01_P-001" (solid, remove dead copper, pour order 17): 49.657,58.885 49.657,50.8 48.514,49.657 39.218,49.657 38.837,49.276 38.837,43.459 41.097,41.199 47.066,41.199 48.971,39.294 48.971,31.902 47.777,30.709 39.167,30.709 38.633,30.175 38.633,21.285 39.268,20.65 48.616,20.65 49.276,19.99 49.276,12.979 48.539,12.243 31.318,12.243 30.632,11.557 30.632,1.626 31.217,1.041 57.887,1.041 57.988,1.143 57.988,58.869
GND on Bottom Layer "GND_L04_P065" (solid, remove dead copper, pour order 65): 71.526,82.855 71.374,7.112 78.511,7.112 80.67,4.953 80.67,0.356 81.001,0.025 126.086,0.025 127.838,1.778 127.838,5.08 129.87,7.112 135.103,7.112 135.103,82.855 129.997,82.855 127.838,85.014 127.838,88.646 126.543,89.941 80.67,89.941 80.67,85.039 78.486,82.855
GND on Bottom Layer "GND_L04_P066" (solid, remove dead copper, pour order 66): 70.663,47.371 70.663,32.08 73.05,32.08 73.05,47.371
IBS+ on Bottom Layer "IBS+_L04_P015" (solid, remove dead copper, pour order 15): 29.083,57.277 31.039,59.233 49.174,59.233 49.555,58.852 49.555,51.003 48.362,49.809 39.04,49.809 38.405,49.174 38.405,43.434 40.894,40.945 46.584,40.945 48.666,38.862 48.666,32.309 47.346,30.988 39.065,30.988 39.014,31.039 38.405,30.429 38.405,20.955 39.116,20.244 48.542,20.244 49.033,19.752 49.022,19.741 49.022,13.03 48.438,12.446 30.912,12.446 29.083,14.275
GND on Bottom Layer "NONET_L-01_P-001" (solid, remove dead copper, pour order 31): 58.268,60.3 58.268,1.118 58.445,0.94 71.069,0.94 71.247,1.118 71.247,60.808 58.776,60.808
GND on Bottom Layer "NONET_L-01_P-001" (solid, remove dead copper, pour order 45): 1.041,82.982 1.041,71.069 1.295,70.815 18.415,70.815 20.396,72.796 49.098,72.796 51.765,75.463 51.841,75.387 71.349,75.387 71.349,88.875 70.968,89.256 30.886,89.256 30.632,89.002 30.632,85.014 28.778,83.16 25.222,83.16 23.368,85.014 23.368,89.586 7.137,89.586 7.137,84.988 5.131,82.982
VPX_U on Bottom Layer "NONET_L-01_P-001" (solid, remove dead copper, pour order 20): 1.067,22.809 1.067,7.239 28.092,7.239 28.702,7.849 28.702,22.301 28.194,22.809 27.889,22.809
VPX_W on Bottom Layer "NONET_L-01_P-001" (solid, remove dead copper, pour order 18): 27.915,56.032 1.016,56.032 1.016,38.735 27.94,38.735 28.473,39.268 28.473,55.474
KL30 on Bottom Layer "NONET_L-01_P-001" (solid, remove dead copper, pour order 32): 1.118,70.587 1.118,56.54 27.711,56.54 28.575,57.404 28.575,60.706 18.669,70.612 1.143,70.612
VPX_V on Bottom Layer "NONET_L-01_P-001" (solid, remove dead copper, pour order 19): 1.041,38.318 1.041,23.317 28.092,23.317 28.524,23.749 28.524,37.871 28.158,38.238
VBAT_D on L3 "VBAT_D_L03_P050" (solid, remove dead copper, pour order 50): 17.297,71.044 16.942,70.688 16.942,7.29 17.043,7.188 28.931,7.188 30.658,5.461 30.658,1.549 31.293,0.914 31.318,0.94 56.464,0.94 57.074,1.549 57.074,60.503 58.064,61.493 70.917,61.493 71.171,61.747 71.171,74.549 51.46,74.549 49.809,72.898 19.152,72.898
GND on L3 "GND_L03_P064" (solid, remove dead copper, pour order 64): 71.399,82.855 71.399,7.112 78.511,7.112 80.67,4.953 80.67,0.356 81.001,0.025 126.086,0.025 127.838,1.778 127.838,5.08 129.87,7.112 135.103,7.112 135.103,82.855 129.997,82.855 127.838,85.014 127.838,88.646 126.543,89.941 80.67,89.941 80.67,85.039 78.486,82.855
GND on L3 "GND_L03_P051" (solid, remove dead copper, pour order 51): 57.785,60.3 57.785,1.27 57.988,1.067 71.171,1.067 71.323,1.219 71.298,1.245 71.298,61.036 58.522,61.036
IBS+ on L3 "NONET_L-01_P-001" (solid, remove dead copper, pour order 24): 37.948,40.462 37.338,40.462 36.881,40.005 36.881,32.029 38.202,30.709 47.93,30.709 49.251,32.029 49.251,39.802 48.618,40.434
IBS+ on L3 "NONET_L-01_P-001" (solid, remove dead copper, pour order 23): 37.135,58.674 36.601,58.141 36.601,50.902 37.44,50.063 48.59,50.063 49.53,51.003 49.53,58.141 48.997,58.674
VBAT1 on L3 "NONET_L-01_P-001" (solid, remove dead copper, pour order 33): 36.246,88.316 36.246,73.508 50.013,73.508 51.74,75.235 71.145,75.235 71.145,88.316
IBS+ on L3 "IBS+_L03_P046" (solid, remove dead copper, pour order 46): 38.354,19.71 38.354,12.7 38.532,12.522 48.006,12.522 48.59,13.106 48.59,19.837 47.549,20.879 39.548,20.879 38.76,20.091
GND on L3 "GND_L03_P060" (solid, remove dead copper, pour order 60): 30.582,89.51 30.582,84.328 32.918,84.328 35.789,87.198 35.789,89.256 35.535,89.51
VPX_U on L3 "VPX_U_L03_P056" (solid, remove dead copper, pour order 56): 1.041,22.733 1.041,7.163 16.535,7.163 16.662,7.29 16.662,22.682 16.485,22.86 1.168,22.86
VPX_V on L3 "VPX_V_L03_P055" (solid, remove dead copper, pour order 55): 1.067,38.252 1.067,23.317 16.637,23.317 16.739,23.419 16.739,37.973 16.459,38.252
VPX_W on L3 "VPX_W_L03_P054" (solid, remove dead copper, pour order 54): 1.041,56.032 1.041,38.684 16.612,38.684 16.713,38.786 16.713,55.905 16.586,56.032
KL30 on L3 "KL30_L03_P053" (solid, remove dead copper, pour order 53): 1.118,70.637 1.067,70.587 1.067,56.54 16.332,56.54 16.535,56.744 16.535,70.358 16.256,70.637
VPX_W on L3 "VPX_W_L03_P049" (solid, remove dead copper, pour order 49): 23.876,53.492 23.876,49.073 27.838,49.073 27.838,53.492
VPX_V on L3 "VPX_V_L03_P048" (solid, remove dead copper, pour order 48): 23.876,35.623 23.876,31.204 27.838,31.204 27.838,35.623
VPX_U on L3 "VPX_U_L03_P047" (solid, remove dead copper, pour order 47): 23.876,17.755 23.876,13.335 27.838,13.335 27.838,17.755
GND on L3 "NONET_L-01_P-001" (solid, remove dead copper, pour order 34): 0.965,82.931 0.965,71.069 1.092,70.942 18.567,70.942 20.726,73.101 35.408,73.101 35.789,73.482 35.789,87.198 34.372,88.615 28.791,83.16 25.222,83.16 23.368,85.014 23.368,89.306 7.163,89.306 7.163,85.039 5.055,82.931
GND on GND "NONET_L-01_P-001" (solid, remove dead copper, pour order 43): 1.092,82.906 1.092,7.442 1.372,7.163 29.032,7.163 30.937,5.258 30.937,1.397 31.369,0.965 71.069,0.965 71.247,1.143 71.247,89.51 31.115,89.51 30.582,88.976 30.582,84.938 28.804,83.16 25.171,83.16 23.343,84.988 23.343,88.646 22.377,89.611 7.569,89.611 7.163,89.205 7.163,85.039 5.105,82.982 1.168,82.982
GND on GND "GND_L02_P062" (solid, remove dead copper, pour order 62): 71.577,82.855 71.425,7.112 78.511,7.112 80.67,4.953 80.67,0.356 81.001,0.025 126.086,0.025 127.838,1.778 127.838,5.08 129.87,7.112 135.103,7.112 135.103,82.855 129.997,82.855 127.838,85.014 127.838,88.646 126.543,89.941 80.67,89.941 80.67,85.039 78.486,82.855
IBS+ on GND "IBS+_L02_P016" (solid, remove dead copper, pour order 16): 29.083,57.861 30.455,59.233 49.174,59.233 50.013,58.395 50.013,13.513 48.946,12.446 30.912,12.446 29.083,14.275
VBAT_D on GND "NONET_L-01_P-001" (solid, remove dead copper, pour order 44): 56.234,70.053 60.374,70.053 60.374,73.838 56.234,73.838
VBAT_D on GND "NONET_L-01_P-001" (solid, remove dead copper, pour order 42): 39.116,49.119 39.116,44.979 42.901,44.979 42.901,49.119
VBAT_D on GND "NONET_L-01_P-001" (solid, remove dead copper, pour order 41): 39.116,29.87 39.116,25.73 42.901,25.73 42.901,29.87
VBAT_D on GND "NONET_L-01_P-001" (solid, remove dead copper, pour order 38): 38.151,12.065 37.744,11.659 37.744,7.366 38.43,6.68 46.33,6.68 48.717,9.068 48.717,12.065
VPX_U on GND "NONET_L-01_P-001" (solid, remove dead copper, pour order 37): 23.774,17.78 23.774,13.411 27.737,13.411 27.737,17.78
VPX_V on GND "NONET_L-01_P-001" (solid, remove dead copper, pour order 36): 23.774,35.649 23.774,31.28 27.737,31.28 27.737,35.649
VPX_W on GND "NONET_L-01_P-001" (solid, remove dead copper, pour order 35): 23.774,53.518 23.774,49.149 27.737,49.149 27.737,53.518

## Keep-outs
Keep-Out Layer:
  circle w0.15: c27,3.5 r1.75
  circle w0.15: c77,3.5 r1.75
  circle w0.15: c77,86.5 r1.75
  circle w0.15: c27,86.5 r1.75
  lines w0.1: 0,3.448 ccw(c3.5,3.5) 3.5,0 ; 0,86.5 cw(c3.5,86.5) 3.448,90 ; 131.5,90 cw(c131.5,86.5) 135,86.552 ; 131.552,0 ccw(c131.5,3.5) 135,3.5 ; 0,0 0,90 135,90 135,0 0,0

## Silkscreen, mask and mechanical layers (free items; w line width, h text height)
Top Overlay:
  drawing of 1566 lines, arcs and shapes, not listed
  text "VBAT1" at 42.34,88.517 h1
  text "GND" at 116.203,88.441 h1
  text "VBAT" at 101.471,88.416 h1
  text "VDD5" at 121.004,78.916 h1
  text "BOOT" at 130.3,78.916 h1
  text "EVB_SPD1179DPW48_V2.1" at 80.339,77.268 h1
  text "TRSTn" at 120.466,76.352 h1
  text "GND" at 130.3,76.352 h1
  text "20240712" at 85.471,75.487 h1
  text "GND" at 19.509,74.747 h2 r90
  text "TDI" at 122.666,73.787 h1
  text "GND" at 130.3,73.787 h1
  text "SWD" at 121.532,71.222 h1
  text "RX" at 130.3,71.222 h1
  text "SWC" at 121.485,68.657 h1
  text "TX" at 130.3,68.657 h1
  text "TDO" at 121.904,66.093 h1
  text "XRSTn" at 130.3,66.093 h1
  text "VDD5" at 121.004,63.528 h1
  text "GND" at 130.3,63.528 h1
  text "VBAT_IN" at 19.486,60.625 h2 r90
  text "5VCOM" at 125.046,56.336 h1 r90
  text "CANH" at 130.529,53.211 h1
  text "CANL" at 130.577,50.544 h1
  text "VDD5EXT" at 124.357,47.395 h1
  text "W" at 19.507,45.168 h2 r90
  text "PWM/LIN" at 124.636,42.229 h1
  text "IO12" at 121.87,34.441 h1
  text "LED2" at 130.275,34.441 h1
  text "IO13" at 121.87,31.89 h1
  text "LED1" at 130.275,31.89 h1
  text "V" at 19.507,30.43 h2 r90
  text "IO14" at 121.823,29.338 h1
  text "MCUFG" at 130.275,29.338 h1
  text "ADC4" at 120.88,26.787 h1
  text "D2S" at 130.275,26.787 h1
  text "IDC/-" at 130.275,24.378 h1
  text "ADC3" at 120.928,24.236 h1
  text "IW/-" at 130.275,21.827 h1
  text "ADC2" at 120.928,21.684 h1
  text "ADC1" at 121.356,19.133 h1
  text "IV" at 130.275,19.133 h1
  text "ADC0" at 120.928,16.582 h1
  text "IU" at 130.275,16.582 h1
  text "U" at 19.486,15.538 h2 r90
  text "NC" at 122.818,14.03 h1
  text "NC" at 130.275,14.03 h1
  text "NC" at 122.818,11.479 h1
  text "NC" at 130.275,11.479 h1
  text "VBAT" at 71.982,10.539 h1
  text "MON" at 76.021,10.539 h1
  text "GND" at 79.602,10.539 h1
  text "GND" at 115.848,2.767 h1
Bottom Solder:
  rectangle: 39.211,6.788 44.266,11.817
  rectangle: 39.211,25.036 44.266,30.066
  rectangle: 22.955,12.916 28.01,17.945
  rectangle: 22.955,30.785 28.01,35.814
  rectangle: 39.211,44.285 44.266,49.314
  rectangle: 22.955,48.654 28.01,53.683
  rectangle: 55.804,69.266 60.858,74.295
Mechanical 1:
  circle w0.15: c27,86.5 r1.75
  circle w0.15: c27,3.5 r1.75
  circle w0.15: c77,3.5 r1.75
  circle w0.15: c77,86.5 r1.75
  lines w0.1: 0,3.448 ccw(c3.5,3.5) 3.5,0 ; 0,86.5 cw(c3.5,86.5) 3.448,90 ; 131.5,90 cw(c131.5,86.5) 135,86.552 ; 131.552,0 ccw(c131.5,3.5) 135,3.5 ; 0,0 135,0 135,90 0,90 0,0
Mechanical 15:
  lines w0.1: 26.746,3.5 27,3.5 ; 26.8,86.5 27,86.5 ; 27,3.266 27,3.5 ; 27,3.734 27,3.5 ; 27,86.266 27,86.5 ; 27,86.72 27,86.5 ; 27.254,3.5 27,3.5 ; 27.254,86.5 27,86.5 ; 76.766,3.5 77,3.5 ; 76.766,86.5 77,86.5 ; 77,3.246 77,3.5 ; 77,3.734 77,3.5 ; 77,86.246 77,86.5 ; 77,86.8 77,86.5 ; 77.25,86.5 77,86.5 ; 77.272,3.5 77,3.5 ; 84.5,0 19.5,0 19.5,90 84.5,90 ; 84.502,-0.051 84.602,89.949
  lines w0.254: 120.269,-0.102 120.269,89.713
